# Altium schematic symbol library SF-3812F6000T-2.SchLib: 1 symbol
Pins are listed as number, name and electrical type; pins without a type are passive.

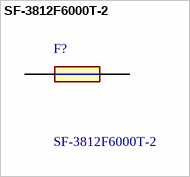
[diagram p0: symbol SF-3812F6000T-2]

## SF-3812F6000T-2
designator F?
Surface Mount Fuses Singlfuse 3812 fast-acting 250V AC 60A; Manufacturer_Name: Bourns; Geometry.Height: 3.3mm
footprint FUSC10131X330N
pins: 1, 2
